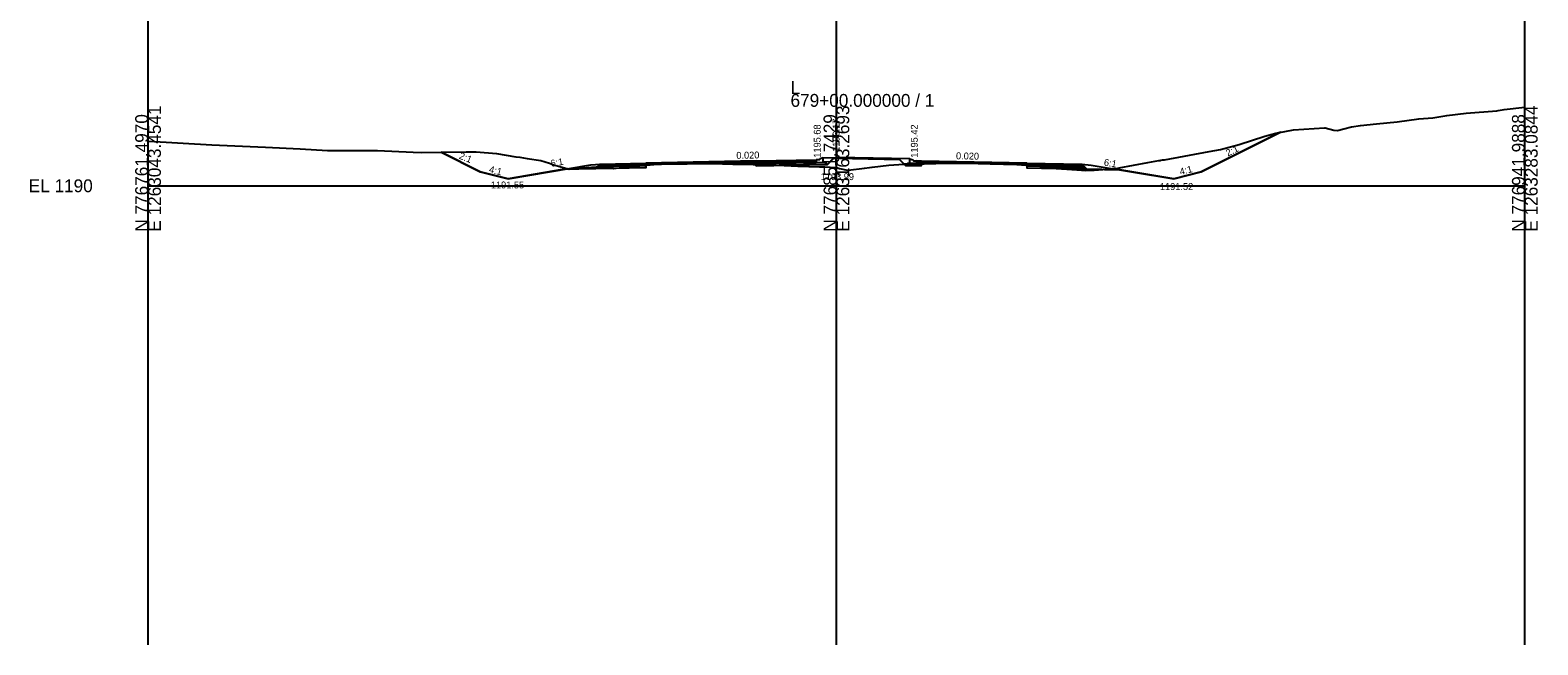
# Model space of a CAD drawing. Extents: x -41 to 1262860, y -100 to 777489.
# Drawn here: x 474.3 to 802.8, y 2745 to 2878.9 of the extents above; entities that cross this region are included whole.
import ezdxf

# ---------------------------------------------------------------- set-up
doc = ezdxf.new("R2010")
doc.units = 0
for name, color, linetype in [('Exist Cross Section Cell', 7, 'Continuous'), ('Exist XS Center Line Elevation Label', 7, 'Continuous'), ('Exist XS Ground Line', 7, 'Continuous'), ('Prop CMT Pvmt Course 1', 7, 'Continuous'), ('Prop CMT Pvmt Surface', 7, 'Continuous'), ('Prop CMT Shld Paved Course 1', 7, 'Continuous'), ('Prop CMT Shld Paved Course 2', 7, 'Continuous'), ('Prop CMT Shld Paved Course 4', 7, 'Continuous'), ('Prop CMT Subgrade Earthwork', 7, 'Continuous'), ('Prop Conc Curb and Gutter', 7, 'Continuous'), ('Prop Conc Island Cover', 7, 'Continuous'), ('Prop XS Ditch Standard Text', 7, 'Continuous'), ('Prop XS Earthwork Shape', 7, 'Continuous'), ('Prop XS Elevation Labels', 7, 'Continuous'), ('Prop XS Exc Vertical Line 1', 7, 'Continuous'), ('Prop XS Exc Vertical Line 2', 7, 'Continuous'), ('Prop XS Exc Vertical Line 3', 7, 'Continuous'), ('Prop XS Finish Grade', 7, 'Continuous'), ('Prop XS Hydro Elevations', 7, 'Continuous'), ('Prop XS SE Text', 7, 'Continuous'), ('Prop XS Side Slope Text', 7, 'Continuous'), ('Scratch_Level_4', 7, 'Continuous'), ('Scratch_Level_6', 7, 'Continuous')]:
    doc.layers.add(name, color=color, linetype=linetype)

msp = doc.modelspace()

# ---------------------------------------------------------------- linework, layer by layer
at = {"layer": 'Exist Cross Section Cell'}
for p, q in [((650, 2845), (650, 2865)), ((500, 2845), (650, 2845)), ((650, 2845), (800, 2845))]:
    msp.add_line(p, q, dxfattribs=at)
at = {"layer": 'Exist XS Ground Line'}
msp.add_lwpolyline([(500, 2854.73), (500.18, 2854.72), (513.89, 2853.9), (525.6, 2853.41), (533.15, 2853.08), (539.08, 2852.69), (543.8, 2852.69), (550, 2852.65), (557.74, 2852.33), (559.63, 2852.27), (564.14, 2852.34), (569.3, 2852.4), (570.47, 2852.43), (571.51, 2852.37), (575.92, 2852.04), (580.15, 2851.31), (581, 2851.2), (582.62, 2850.96), (585.6, 2850.5), (587.46, 2849.91), (588.59, 2849.48), (589.42, 2849.26), (591.73, 2848.65), (595.59, 2848.95), (597.68, 2849.14), (599.99, 2849.17), (600.14, 2849.17), (600.17, 2849.16), (601.42, 2848.8), (603.21, 2848.96), (603.47, 2849), (606.42, 2849.27), (610.93, 2849.69), (617.49, 2849.76), (622.9, 2849.83), (628.09, 2849.7), (635.63, 2849.54), (641.6, 2849.3), (646.29, 2849.14), (647.46, 2849.1), (648.63, 2849.07), (650.01, 2848.99), (650.67, 2848.79), (652.41, 2848.43), (652.59, 2848.37), (656.14, 2848.86), (657.22, 2848.98), (657.75, 2849.06), (661.45, 2849.52), (663.57, 2849.63), (665.55, 2849.74), (671.66, 2849.82), (678.24, 2849.92), (683.51, 2849.79), (689.32, 2849.65), (691.27, 2849.52), (693.26, 2849.4), (696.57, 2848.95), (697.93, 2848.75), (702.39, 2848.44), (704.33, 2848.3), (706.17, 2848.42), (710.96, 2848.8), (711.6, 2848.91), (717.83, 2850.04), (720.24, 2850.48), (720.53, 2850.53), (720.68, 2850.55), (721.07, 2850.62), (721.45, 2850.67), (731.2, 2852.45), (733.71, 2852.9), (737.73, 2853.98), (743.32, 2855.78), (745.77, 2856.47), (747.71, 2856.84), (749.62, 2857.18), (756.32, 2857.59), (756.5, 2857.61), (758.42, 2857.11), (759.21, 2857.03), (760.59, 2857.41), (762.26, 2857.82), (764.18, 2858.13), (767.66, 2858.51), (772.18, 2858.95), (776.89, 2859.58), (779.95, 2859.81), (783, 2860.31), (787.21, 2860.82), (793.88, 2861.34), (794.19, 2861.39), (795.52, 2861.59), (800, 2862.1)], dxfattribs=at)
at = {"layer": 'Prop CMT Pvmt Course 1'}
for p, q in [((632.5, 2850.15), (645.61, 2850.42)), ((645.61, 2850.42), (645.61, 2850.67)), ((667.5, 2850.4), (667.5, 2850.15)), ((668.5, 2850.13), (667.5, 2850.15))]:
    msp.add_line(p, q, dxfattribs=at)
for points in [[(608.5, 2849.92), (608.5, 2849.67), (632.5, 2850.15), (632.5, 2850.15), (632.5, 2850.4), (632.5, 2850.4), (632.5, 2850.4), (608.5, 2849.92), (608.5, 2849.92)], [(691.5, 2849.92), (691.5, 2849.92), (668.5, 2850.38), (668.5, 2850.38), (668.5, 2850.38), (668.5, 2850.38), (668.5, 2850.13), (668.5, 2850.13), (668.5, 2850.13), (691.5, 2849.67), (691.5, 2849.92)]]:
    msp.add_lwpolyline(points, dxfattribs=at)
at = {"layer": 'Prop CMT Pvmt Surface'}
for p, q in [((598.5, 2849.72), (608.5, 2849.92)), ((608.5, 2849.92), (632.5, 2850.4)), ((632.5, 2850.4), (645.61, 2850.67)), ((668.5, 2850.38), (667.5, 2850.4)), ((668.5, 2850.38), (691.5, 2849.92)), ((691.5, 2849.92), (703.5, 2849.68))]:
    msp.add_line(p, q, dxfattribs=at)
at = {"layer": 'Prop CMT Shld Paved Course 1'}
for p, q in [((598.24, 2849.47), (598.5, 2849.72)), ((608.5, 2849.67), (598.24, 2849.47)), ((604.5, 2849.84), (604.5, 2849.84)), ((608.5, 2849.92), (608.5, 2849.92)), ((608.5, 2849.92), (608.5, 2849.92)), ((608.5, 2849.92), (608.5, 2849.67)), ((608.5, 2849.67), (608.5, 2849.67)), ((691.5, 2849.92), (691.5, 2849.92)), ((691.5, 2849.92), (691.5, 2849.92)), ((691.5, 2849.92), (691.5, 2849.67)), ((691.5, 2849.67), (691.5, 2849.67)), ((691.5, 2849.67), (703.76, 2849.43)), ((695.5, 2849.84), (695.5, 2849.84)), ((703.76, 2849.43), (703.5, 2849.68))]:
    msp.add_line(p, q, dxfattribs=at)
at = {"layer": 'Prop CMT Shld Paved Course 2'}
for p, q in [((597.9, 2849.13), (598.24, 2849.47)), ((608.5, 2849.34), (597.9, 2849.13)), ((604.24, 2849.59), (604.24, 2849.59)), ((610.93, 2849.72), (608.5, 2849.67)), ((608.5, 2849.46), (610.93, 2849.69)), ((608.5, 2849.67), (608.5, 2849.67)), ((608.5, 2849.67), (608.5, 2849.67)), ((608.5, 2849.67), (608.5, 2849.34)), ((608.5, 2849.67), (608.5, 2849.67)), ((608.5, 2849.67), (608.5, 2849.46)), ((608.5, 2849.34), (608.5, 2849.34)), ((617.49, 2849.85), (610.93, 2849.72)), ((610.93, 2849.69), (617.49, 2849.76)), ((610.93, 2849.72), (610.93, 2849.72)), ((610.93, 2849.72), (610.93, 2849.72)), ((610.93, 2849.69), (610.93, 2849.69)), ((610.93, 2849.69), (610.93, 2849.69)), ((622.9, 2849.96), (617.49, 2849.85)), ((617.49, 2849.85), (617.49, 2849.85)), ((617.49, 2849.76), (622.9, 2849.83)), ((617.49, 2849.76), (617.49, 2849.76)), ((628.09, 2850.07), (622.9, 2849.96)), ((622.9, 2849.83), (627.39, 2849.72)), ((627.39, 2849.72), (628.09, 2849.73)), ((627.39, 2849.72), (627.39, 2849.72)), ((632.5, 2850.15), (628.09, 2850.07)), ((628.09, 2850.07), (628.09, 2850.07)), ((628.09, 2849.73), (632.5, 2849.82)), ((628.09, 2849.73), (628.09, 2849.73)), ((632.5, 2849.82), (632.5, 2850.15)), ((632.5, 2850.15), (632.5, 2850.15)), ((632.5, 2849.82), (645.61, 2850.08)), ((645.61, 2850.42), (645.61, 2850.08)), ((645.61, 2850.08), (645.61, 2850.08)), ((667.5, 2849.82), (667.5, 2850.15)), ((668.5, 2849.8), (667.5, 2849.82)), ((671.66, 2850.07), (668.5, 2850.13)), ((668.5, 2850.13), (668.5, 2850.13)), ((668.5, 2850.13), (668.5, 2850.13)), ((668.5, 2850.13), (668.5, 2849.8)), ((668.5, 2849.8), (668.5, 2849.8)), ((668.5, 2849.8), (669.1, 2849.79)), ((669.1, 2849.79), (671.66, 2849.82)), ((669.1, 2849.79), (669.1, 2849.79)), ((678.24, 2849.94), (671.66, 2850.07)), ((671.66, 2850.07), (671.66, 2850.07)), ((671.66, 2849.82), (678.24, 2849.92)), ((671.66, 2849.82), (671.66, 2849.82)), ((683.51, 2849.83), (678.24, 2849.94)), ((678.24, 2849.94), (678.24, 2849.94)), ((678.24, 2849.92), (678.24, 2849.92)), ((678.24, 2849.92), (683.51, 2849.79)), ((689.32, 2849.72), (683.51, 2849.83)), ((683.51, 2849.83), (683.51, 2849.83)), ((683.51, 2849.79), (683.51, 2849.79)), ((683.51, 2849.79), (689.32, 2849.65)), ((691.27, 2849.68), (689.32, 2849.72)), ((689.32, 2849.72), (689.32, 2849.72)), ((689.32, 2849.72), (689.32, 2849.72)), ((689.32, 2849.65), (689.32, 2849.65)), ((689.32, 2849.65), (689.32, 2849.65)), ((689.32, 2849.65), (691.27, 2849.52)), ((691.5, 2849.67), (691.27, 2849.68)), ((691.27, 2849.68), (691.27, 2849.68)), ((691.27, 2849.52), (691.27, 2849.52)), ((691.27, 2849.52), (691.5, 2849.51)), ((691.5, 2849.67), (691.5, 2849.67)), ((691.5, 2849.67), (691.5, 2849.67)), ((691.5, 2849.67), (691.5, 2849.34)), ((691.5, 2849.51), (691.5, 2849.67)), ((691.5, 2849.67), (691.5, 2849.67)), ((691.5, 2849.34), (691.5, 2849.34)), ((691.5, 2849.34), (704.1, 2849.09)), ((704.1, 2849.09), (703.76, 2849.43))]:
    msp.add_line(p, q, dxfattribs=at)
at = {"layer": 'Prop CMT Shld Paved Course 4'}
for p, q in [((597.9, 2849.13), (597.44, 2848.66)), ((608.5, 2848.88), (597.44, 2848.66)), ((603.4, 2849.24), (603.4, 2849.24)), ((603.9, 2849.25), (603.9, 2849.25)), ((608.5, 2849.34), (608.5, 2849.34)), ((608.5, 2849.34), (608.5, 2849.34)), ((608.5, 2849.34), (608.5, 2848.88)), ((628.09, 2849.7), (627.39, 2849.72)), ((628.09, 2849.7), (632.5, 2849.61)), ((632.5, 2849.82), (632.5, 2849.36)), ((632.5, 2849.36), (648.06, 2849.67)), ((645.61, 2850.08), (647.61, 2850.12)), ((647.61, 2850.12), (648.06, 2849.67)), ((665.5, 2849.86), (665.05, 2849.41)), ((668.5, 2849.34), (665.05, 2849.41)), ((667.5, 2849.82), (665.5, 2849.86)), ((668.5, 2849.34), (668.5, 2849.8)), ((669.1, 2849.79), (668.5, 2849.78)), ((691.5, 2849.34), (691.5, 2849.34)), ((691.5, 2849.34), (691.5, 2849.34)), ((691.5, 2849.34), (691.5, 2848.88)), ((691.5, 2848.88), (704.56, 2848.62)), ((704.56, 2848.62), (704.1, 2849.09))]:
    msp.add_line(p, q, dxfattribs=at)
at = {"layer": 'Prop CMT Subgrade Earthwork'}
for p, q in [((608.5, 2848.88), (590.22, 2848.52)), ((608.5, 2848.88), (608.5, 2849.46)), ((648.06, 2849.67), (632.5, 2849.36)), ((632.5, 2849.36), (632.5, 2849.61)), ((648.06, 2849.67), (649.55, 2851.16)), ((665.05, 2849.41), (663.56, 2850.9)), ((665.05, 2849.41), (668.5, 2849.34)), ((668.5, 2849.34), (668.5, 2849.78)), ((691.5, 2849.51), (691.5, 2848.88)), ((691.5, 2848.88), (711.78, 2848.48))]:
    msp.add_line(p, q, dxfattribs=at)
at = {"layer": 'Prop Conc Curb and Gutter'}
for p, q in [((646.3, 2850.68), (645.61, 2850.67)), ((645.61, 2850.67), (645.61, 2850.08)), ((645.61, 2850.08), (647.11, 2850.11)), ((646.36, 2850.76), (646.36, 2850.74)), ((647.11, 2851.11), (646.46, 2850.9)), ((647.11, 2850.11), (647.11, 2851.11)), ((647.11, 2850.11), (647.11, 2850.11)), ((666, 2850.85), (666.65, 2850.63)), ((666, 2849.85), (666, 2850.85)), ((667.5, 2849.82), (666, 2849.85)), ((666.75, 2850.5), (666.75, 2850.48)), ((666.81, 2850.42), (667.5, 2850.4)), ((667.5, 2849.82), (667.5, 2850.4))]:
    msp.add_line(p, q, dxfattribs=at)
for centre, radius, start, end in [((646.3, 2850.74), 0.0625, 271.1458, 360), ((646.5, 2850.76), 0.146, 108.435, 180), ((666.6, 2850.5), 0.146, 0, 71.565), ((666.81, 2850.48), 0.0625, 180, 268.8542)]:
    msp.add_arc(centre, radius, start, end, dxfattribs=at)
at = {"layer": 'Prop Conc Island Cover'}
for p, q in [((647.11, 2851.11), (650, 2851.17)), ((647.11, 2850.85), (647.11, 2850.85)), ((666, 2850.85), (650, 2851.17))]:
    msp.add_line(p, q, dxfattribs=at)
at = {"layer": 'Prop XS Earthwork Shape'}
for points in [[(720.68, 2850.55), (721.07, 2850.62), (721.45, 2850.67), (731.2, 2852.45), (733.71, 2852.9), (737.73, 2853.98), (743.32, 2855.78), (745.77, 2856.47), (746.77, 2856.66), (729.5, 2848.02), (723.5, 2846.52), (711.78, 2848.48), (710.2, 2848.74), (710.96, 2848.8), (711.6, 2848.91), (717.83, 2850.04), (720.24, 2850.48), (720.53, 2850.53)], [(563.86, 2852.33), (564.14, 2852.34), (569.3, 2852.4), (570.47, 2852.43), (571.51, 2852.37), (575.92, 2852.04), (580.15, 2851.31), (581, 2851.2), (582.62, 2850.96), (585.6, 2850.5), (587.46, 2849.91), (588.59, 2849.48), (589.42, 2849.26), (591.44, 2848.72), (590.22, 2848.52), (578.44, 2846.55), (572.4, 2848.06)], [(597.68, 2849.14), (597.92, 2849.14), (597.44, 2848.66), (590.22, 2848.52), (591.44, 2848.72), (591.73, 2848.65), (595.59, 2848.95)], [(606.42, 2849.27), (608.5, 2849.46), (608.5, 2848.88), (597.44, 2848.66), (597.92, 2849.14), (599.99, 2849.17), (600.14, 2849.17), (600.17, 2849.16), (601.42, 2848.8), (603.21, 2848.96), (603.47, 2849)], [(632.5, 2849.61), (635.63, 2849.54), (637.55, 2849.46), (632.5, 2849.36)], [(664.76, 2849.7), (663.82, 2850.65), (650, 2850.92), (649.29, 2850.91), (648.06, 2849.67), (637.55, 2849.46), (641.6, 2849.3), (646.29, 2849.14), (647.46, 2849.1), (648.63, 2849.07), (650.01, 2848.99), (650.67, 2848.79), (652.41, 2848.43), (652.59, 2848.37), (656.14, 2848.86), (657.22, 2848.98), (657.75, 2849.06), (661.45, 2849.52), (663.57, 2849.63)], [(668.5, 2849.34), (668.5, 2849.78), (665.55, 2849.74), (664.76, 2849.7), (665.05, 2849.41)], [(691.5, 2849.51), (691.5, 2848.88), (697.89, 2848.76), (696.57, 2848.95), (693.26, 2849.4)], [(702.39, 2848.44), (704.33, 2848.3), (706.17, 2848.42), (707.85, 2848.56), (704.56, 2848.62), (697.89, 2848.76), (697.93, 2848.75)], [(707.85, 2848.56), (710.2, 2848.74), (711.78, 2848.48)]]:
    msp.add_lwpolyline(points, close=True, dxfattribs=at)
at = {"layer": 'Prop XS Exc Vertical Line 1'}
msp.add_line((500, 2745), (500, 2945), dxfattribs=at)
at = {"layer": 'Prop XS Exc Vertical Line 2'}
msp.add_line((650, 2745), (650, 2945), dxfattribs=at)
at = {"layer": 'Prop XS Exc Vertical Line 3'}
msp.add_line((800, 2745), (800, 2945), dxfattribs=at)
at = {"layer": 'Prop XS Finish Grade'}
for p, q in [((729.5, 2848.02), (746.77, 2856.66)), ((563.86, 2852.33), (572.4, 2848.06)), ((578.44, 2846.55), (596.5, 2849.56)), ((596.5, 2849.56), (598.5, 2849.72)), ((598.5, 2849.72), (597.44, 2848.66)), ((703.5, 2849.68), (705.5, 2849.52)), ((703.5, 2849.68), (704.56, 2848.62)), ((705.5, 2849.52), (723.5, 2846.52)), ((572.4, 2848.06), (578.44, 2846.55)), ((723.5, 2846.52), (729.5, 2848.02))]:
    msp.add_line(p, q, dxfattribs=at)
at = {"layer": 'Scratch_Level_4'}
msp.add_line((800, 2745), (800, 2945), dxfattribs=at)
at = {"layer": 'Scratch_Level_6'}
msp.add_line((500, 2745), (500, 2945), dxfattribs=at)

# ---------------------------------------------------------------- texts
at = {"layer": 'Exist Cross Section Cell'}
for s, p in [('679+00.000000 / 1', (640, 2862.2)), ('L', (640, 2865)), ('EL 1190', (474, 2843.6))]:
    msp.add_text(s, height=2.8, dxfattribs=at).set_placement(p)
for s, p in [('E 1263043.4541', (502.8, 2835)), ('E 1263163.2693', (652.8, 2835)), ('E 1263283.0844', (802.8, 2835)), ('N 776761.4970', (500, 2835)), ('N 776851.7429', (650, 2835)), ('N 776941.9888', (800, 2835))]:
    msp.add_text(s, height=2.8, rotation=90, dxfattribs=at).set_placement(p)
at = {"layer": 'Exist XS Center Line Elevation Label'}
msp.add_text('1193.99', height=1.5, dxfattribs=at).set_placement((646.57, 2846.24))
at = {"layer": 'Prop XS Ditch Standard Text'}
for s, p in [('1191.55', (574.7, 2844.43)), ('1191.52', (720.49, 2844.08))]:
    msp.add_text(s, height=1.5, dxfattribs=at).set_placement(p)
at = {"layer": 'Prop XS Elevation Labels'}
for s, p in [('1195.68', (646.56, 2851.11)), ('1195.42', (667.72, 2851.11))]:
    msp.add_text(s, height=1.5, rotation=90, dxfattribs=at).set_placement(p)
at = {"layer": 'Prop XS Hydro Elevations'}
msp.add_text('1196.17', height=1.5, rotation=90, dxfattribs=at).set_placement((650.67, 2852.39))
at = {"layer": 'Prop XS SE Text'}
for rotation, p in [(1.1458, (628.2, 2850.87)), (358.8542, (676.04, 2850.79))]:
    msp.add_text('0.020', height=1.5, rotation=rotation, dxfattribs=at).set_placement(p)
at = {"layer": 'Prop XS Side Slope Text'}
for s, rotation, p in [('2:1', 338.2726, (567.63, 2850.96)), ('2:1', 26.5651, (735.29, 2851.36)), ('4:1', 345.9638, (574.19, 2847.93)), ('6:1', 9.4623, (587.83, 2849.12)), ('6:1', 350.5377, (708.19, 2849.43)), ('4:1', 14.0362, (724.98, 2847.31))]:
    msp.add_text(s, height=1.5, rotation=rotation, dxfattribs=at).set_placement(p)

doc.saveas('drawing.dxf')
